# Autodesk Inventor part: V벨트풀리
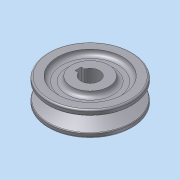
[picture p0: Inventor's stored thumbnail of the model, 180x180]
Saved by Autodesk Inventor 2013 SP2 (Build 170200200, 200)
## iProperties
Created: 2015-03
Part Number: V벨트풀리
Material: 강
Document SubType Name: Modeling
Designer: KYOUNG IL JANG
Density: 1 g/cm^3
CustomPartVersion: 1
Author: KYOUNG IL JANG
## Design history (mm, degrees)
sketch "주 스케치"
  geometry: L1 (0, 16)-(27, 16); L2 (27, 16)-(27, 12.861); L3 (27, 12.861)-(16, 9.498); L4 (16, 9.498)-(16, 6.502); L5 (16, 6.502)-(27, 3.139); L6 (27, 3.139)-(27, 0); L7 (27, 0)-(0, 0); L8 (25, 12.25)-(25, 3.75); L9 (16, 8)-(25, 8); L10 (27, 12.861)-(27, 3.139); L11 (0, -3)-(0, 18) reference; L12 (0, 0)-(0, 16)
  constraints: 22 end point, 5 perpendicular, 2 collinear, 2 midpoint, 2 point on line, 1 parallel
  dimensions: "d0" = 8.5 distance of L8.start L8.end (= da_Bw); "d1" = 34 deg angle of L3 L5 (= da_Alfa); "d2" = 2 distance between parallel lines of L2 L8 (= da_c); "d6" = 16 distance between parallel lines of L7 L1 (computed from d5, da_ng, da_Sg); "d21" = 50 diameter of L8 L11 (= da_Dw); "d25" = 11 distance between parallel lines of L4 L10 (= da_Hd); "d27" = 8 distance between parallel lines of L7 L9 (= da_Se)
node "벨트 평면"
revolve "본체" stored, may be unused: angle "d7" = 90 deg
revolve "그루브" stored, may be unused: angle "d15" = 90 deg
feature "허브 키홈"
fillet "모깎기3" dims "d28" = 0.5, "d29" = 1, "d30" = 1
sketch "스케치2"
  geometry: C1 r 12 at (0, 0); C2 r 21 at (0, 0); 1 further point
  constraints: 2 centre point, 2 coincident
  dimensions: "d31" = 24 diameter of C1; "d32" = 42 diameter of C2
extrude "돌출1" cut sketch "스케치2" distance "d33" = 3; taper "d34" = 0 deg
fillet "모깎기4" dims "d35" = 3
node "작업 평면2"
body "Solid1"
pattern_linear "그루브 패턴" dims "d18" = 12 (= da_Sg)
mirror "대칭1"
other parameters: "d5" = 8 (= da_Se), "da_Bw" = 8.5 [user parameter; used in 1 equation term], "da_Alfa" = 34 deg [user parameter; used in 1 equation term], "da_c" = 2 [user parameter; used in 1 equation term], "da_Dw" = 50 [user parameter; used in 1 equation term], "da_Hd" = 11 [user parameter; used in 1 equation term], "da_Se" = 8 [user parameter; used in 2 equation terms], "da_Sg" = 12 [user parameter; used in 2 equation terms], "da_r1" = 0 [user parameter], "da_r2" = 0 [user parameter], "d24" = 0, "d26" = 0
